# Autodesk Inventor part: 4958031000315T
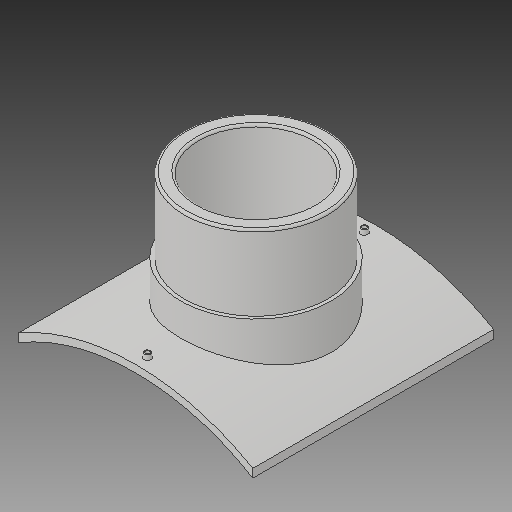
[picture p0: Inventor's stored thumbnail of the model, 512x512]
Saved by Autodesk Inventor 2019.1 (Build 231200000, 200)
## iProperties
Created: 2017-10
Part Number: 4958031000315T
Material: Generic
Description: PLASSON BRANCH SADDLE  1000x315
Document SubType Name: Modeling
Designer: KIM
Mass: 2754.05 g
Surface Area: 3037.44 cm^2
Volume: 2754.05 cm^3
Density: 1 g/cm^3
Appearance: Default
Author: KIM
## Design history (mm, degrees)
derived "495803.ipt"
feature "Solid1::495803.ipt"
tag "TaggingFeature1"
body "Solid1"
other parameters: "d1" = 16, "d2" = 516, "d4" = 0, "d12" = 525.6, "d13" = 14, "d14" = 238.5, "d16" = 5 deg, "d18" = 4, "d19" = 14, "d20" = 0, "d21" = 3, "d22" = 0, "d23" = 752, "d24" = 330.75, "d25" = 16, "d26" = 252, "d28" = 0, "d29" = 9.6, "d31" = 0, "d32" = 118, "d33" = 0, "d36" = 315, "d37" = 165.2, "d38" = 0, "d39" = 5, "d_1" = 315, "B_" = 516, "H_" = 236, "x_" = 16, "D_" = 16
